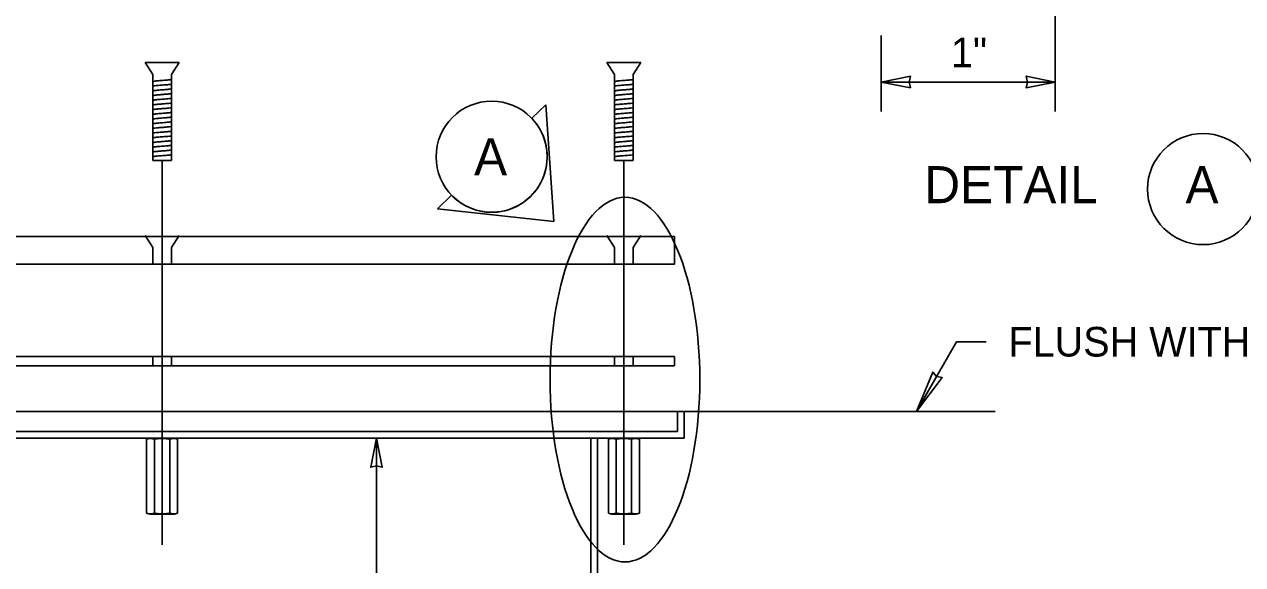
# Model space of a CAD drawing. Extents: x 99862 to 103680, y 99470 to 102076.
# Drawn here: x 101706 to 102364, y 100432 to 100724 of the extents above; entities that cross this region are included whole.
import ezdxf

# ---------------------------------------------------------------- set-up
doc = ezdxf.new("R2010")
doc.units = 0
for name, color, linetype in [('Level 1', 7, 'Continuous'), ('Level 10', 7, 'Continuous'), ('Level 15', 7, 'Continuous'), ('Level 16', 7, 'Continuous'), ('Level 17', 7, 'Continuous'), ('Level 2', 7, 'Continuous'), ('Level 20', 7, 'Continuous')]:
    doc.layers.add(name, color=color, linetype=linetype)

msp = doc.modelspace()

# ---------------------------------------------------------------- linework, layer by layer
at = {"layer": 'Level 1'}
for p, q in [((101248.49, 100515), (102062.21, 100515)), ((102058.64, 100504.1), (102058.64, 100515)), ((102062.21, 100500.54), (102062.21, 100515)), ((102062.21, 100500.54), (101248.49, 100500.54)), ((101252.06, 100504.1), (102058.64, 100504.1)), ((102011.78, 100460.54), (102011.78, 100500.54)), ((102015.35, 100136.47), (102015.35, 100500.54)), ((102011.78, 100400.54), (102011.78, 100460.54))]:
    msp.add_line(p, q, dxfattribs=at)
at = {"layer": 'Level 10'}
for p, q in [((101770.95, 100703.32), (101789.26, 100703.32)), ((101770.95, 100703.32), (101775.1, 100696.87)), ((101789.26, 100703.32), (101785.1, 100696.87)), ((102020.46, 100703.32), (102038.77, 100703.32)), ((102020.46, 100703.32), (102024.62, 100696.87)), ((102038.77, 100703.32), (102034.62, 100696.87)), ((101775.1, 100650.56), (101775.1, 100696.87)), ((101785.1, 100696.87), (101785.1, 100650.56)), ((102024.62, 100650.56), (102024.62, 100696.87)), ((102034.62, 100696.87), (102034.62, 100650.56)), ((101785.1, 100650.56), (101775.1, 100650.56)), ((102034.62, 100650.56), (102024.62, 100650.56)), ((101771.72, 100500.01), (101773.6, 100500.54)), ((101771.72, 100460.03), (101771.72, 100500.01)), ((101772.1, 100500.12), (101773.6, 100500.54)), ((101786.6, 100500.54), (101773.6, 100500.54)), ((101775.91, 100460.03), (101775.91, 100500.01)), ((101784.3, 100460.03), (101784.3, 100500.01)), ((101786.6, 100500.54), (101788.49, 100500.01)), ((101788.49, 100460.03), (101788.49, 100500.01)), ((102021.23, 100500.01), (102023.12, 100500.54)), ((102021.23, 100460.03), (102021.23, 100500.01)), ((102021.62, 100500.12), (102023.12, 100500.54)), ((102021.62, 100500.12), (102023.12, 100500.54)), ((102036.12, 100500.54), (102023.12, 100500.54)), ((102025.42, 100500.01), (102025.42, 100460.01)), ((102025.42, 100460.03), (102025.42, 100500.01)), ((102033.81, 100460.03), (102033.81, 100500.01)), ((102036.12, 100500.54), (102038, 100500.01)), ((102038, 100460.03), (102038, 100500.01)), ((101773.6, 100459.5), (101771.72, 100460.03)), ((101773.6, 100459.5), (101772.1, 100459.92)), ((101786.6, 100459.5), (101773.6, 100459.5)), ((101788.49, 100460.03), (101786.6, 100459.5)), ((102023.12, 100459.5), (102021.23, 100460.03)), ((102023.12, 100459.5), (102021.62, 100459.92)), ((102023.12, 100459.5), (102021.62, 100459.92)), ((102036.12, 100459.5), (102023.12, 100459.5)), ((102038, 100460.03), (102036.12, 100459.5))]:
    msp.add_line(p, q, dxfattribs=at)
for points, degree in [([(101775.11, 100693.12), (101775.2, 100693.18), (101775.75, 100693.32), (101777.96, 100693.54), (101781.5, 100693.81), (101784.15, 100694.05), (101784.95, 100694.2), (101785.1, 100694.26), (101785.11, 100694.26)], 3), ([(101775.11, 100690.59), (101775.16, 100690.62), (101775.43, 100690.71), (101776.64, 100690.89), (101779.52, 100691.13), (101782.66, 100691.37), (101784.46, 100691.57), (101784.97, 100691.67), (101785.11, 100691.72)], 3), ([(102024.62, 100693.12), (102024.71, 100693.18), (102025.26, 100693.32), (102027.47, 100693.54), (102031.01, 100693.81), (102033.66, 100694.05), (102034.46, 100694.2), (102034.61, 100694.26), (102034.62, 100694.26)], 3), ([(102024.62, 100690.59), (102024.68, 100690.62), (102024.94, 100690.71), (102026.16, 100690.89), (102029.03, 100691.13), (102032.17, 100691.37), (102033.97, 100691.57), (102034.48, 100691.67), (102034.62, 100691.72)], 3), ([(101775.11, 100688.05), (101775.13, 100688.06), (101775.35, 100688.17), (101776.63, 100688.35), (101779.25, 100688.57), (101781.72, 100688.76), (101783.91, 100688.95), (101784.88, 100689.1), (101785.1, 100689.18), (101785.11, 100689.19)], 3), ([(101775.11, 100685.51), (101775.16, 100685.55), (101775.5, 100685.65), (101776.73, 100685.81), (101778.93, 100686), (101781.45, 100686.2), (101783.98, 100686.42), (101784.91, 100686.57), (101785.11, 100686.65)], 3), ([(101775.11, 100682.97), (101775.16, 100683.01), (101775.58, 100683.14), (101777.42, 100683.34), (101780.81, 100683.61), (101783.46, 100683.83), (101784.73, 100684), (101785.03, 100684.08), (101785.11, 100684.11)], 3), ([(102024.62, 100688.05), (102024.64, 100688.06), (102024.86, 100688.17), (102026.14, 100688.35), (102028.77, 100688.57), (102031.23, 100688.76), (102033.42, 100688.95), (102034.39, 100689.1), (102034.61, 100689.18), (102034.62, 100689.19)], 3), ([(102024.62, 100685.51), (102024.68, 100685.55), (102025.01, 100685.65), (102026.24, 100685.81), (102028.44, 100686), (102030.96, 100686.2), (102033.49, 100686.42), (102034.42, 100686.57), (102034.62, 100686.65)], 3), ([(102024.62, 100682.97), (102024.68, 100683.01), (102025.09, 100683.14), (102026.93, 100683.34), (102030.32, 100683.61), (102032.97, 100683.83), (102034.24, 100684), (102034.55, 100684.08), (102034.62, 100684.11)], 3), ([(101775.11, 100680.44), (101775.16, 100680.47), (101775.5, 100680.58), (101776.73, 100680.73), (101778.93, 100680.93), (101781.45, 100681.12), (101783.98, 100681.34), (101784.91, 100681.49), (101785.11, 100681.57)], 3), ([(101775.11, 100677.9), (101775.16, 100677.93), (101775.5, 100678.04), (101776.73, 100678.19), (101778.93, 100678.39), (101781.45, 100678.58), (101783.98, 100678.8), (101784.91, 100678.96), (101785.11, 100679.03)], 3), ([(102024.62, 100680.44), (102024.68, 100680.47), (102025.01, 100680.58), (102026.24, 100680.73), (102028.44, 100680.93), (102030.96, 100681.12), (102033.49, 100681.34), (102034.42, 100681.49), (102034.62, 100681.57)], 3), ([(102024.62, 100677.9), (102024.68, 100677.93), (102025.01, 100678.04), (102026.24, 100678.19), (102028.44, 100678.39), (102030.96, 100678.58), (102033.49, 100678.8), (102034.42, 100678.96), (102034.62, 100679.03)], 3), ([(101775.11, 100675.36), (101775.16, 100675.39), (101775.58, 100675.52), (101777.42, 100675.73), (101780.81, 100675.99), (101783.46, 100676.21), (101784.73, 100676.39), (101785.04, 100676.47), (101785.11, 100676.49)], 3), ([(101775.11, 100672.82), (101775.16, 100672.86), (101775.5, 100672.96), (101776.73, 100673.12), (101779.2, 100673.34), (101781.78, 100673.53), (101784.07, 100673.75), (101784.88, 100673.87), (101785.1, 100673.95), (101785.11, 100673.96)], 3), ([(101775.11, 100670.28), (101775.2, 100670.34), (101775.77, 100670.47), (101777.96, 100670.7), (101781.5, 100670.97), (101784.15, 100671.21), (101784.95, 100671.36), (101785.1, 100671.41), (101785.11, 100671.42)], 3), ([(102024.62, 100675.36), (102024.68, 100675.39), (102025.09, 100675.52), (102026.93, 100675.73), (102030.32, 100675.99), (102032.97, 100676.21), (102034.24, 100676.39), (102034.55, 100676.47), (102034.62, 100676.49)], 3), ([(102024.62, 100672.82), (102024.68, 100672.86), (102025.01, 100672.96), (102026.24, 100673.12), (102028.71, 100673.34), (102031.29, 100673.53), (102033.58, 100673.75), (102034.39, 100673.87), (102034.61, 100673.95), (102034.62, 100673.96)], 3), ([(102024.62, 100670.28), (102024.72, 100670.34), (102025.28, 100670.47), (102027.47, 100670.7), (102031.01, 100670.97), (102033.66, 100671.21), (102034.46, 100671.36), (102034.61, 100671.41), (102034.62, 100671.42)], 3), ([(101775.11, 100667.75), (101775.16, 100667.78), (101775.5, 100667.89), (101776.92, 100668.07), (101779.26, 100668.26), (101782.03, 100668.48), (101784.22, 100668.68), (101784.97, 100668.83), (101785.11, 100668.88)], 3), ([(101775.11, 100665.21), (101775.16, 100665.24), (101775.5, 100665.35), (101776.73, 100665.5), (101778.93, 100665.7), (101781.45, 100665.89), (101783.98, 100666.11), (101784.91, 100666.26), (101785.11, 100666.34)], 3), ([(102024.62, 100667.75), (102024.68, 100667.78), (102025.02, 100667.89), (102026.43, 100668.07), (102028.77, 100668.26), (102031.54, 100668.48), (102033.74, 100668.68), (102034.49, 100668.83), (102034.62, 100668.88)], 3), ([(102024.62, 100665.21), (102024.68, 100665.24), (102025.01, 100665.35), (102026.24, 100665.5), (102028.44, 100665.7), (102030.96, 100665.89), (102033.49, 100666.11), (102034.42, 100666.26), (102034.62, 100666.34)], 3), ([(101775.11, 100662.67), (101775.16, 100662.7), (101775.58, 100662.83), (101777.42, 100663.04), (101780.81, 100663.3), (101783.46, 100663.52), (101784.73, 100663.7), (101785.03, 100663.77), (101785.11, 100663.8)], 3), ([(101775.11, 100660.13), (101775.16, 100660.16), (101775.5, 100660.27), (101776.73, 100660.43), (101779.2, 100660.64), (101781.78, 100660.84), (101784.06, 100661.05), (101784.88, 100661.18), (101785.1, 100661.26), (101785.11, 100661.27)], 3), ([(101775.11, 100657.59), (101775.2, 100657.65), (101775.77, 100657.78), (101777.96, 100658.01), (101781.5, 100658.27), (101784.15, 100658.52), (101784.95, 100658.67), (101785.1, 100658.72), (101785.11, 100658.73)], 3), ([(102024.62, 100662.67), (102024.68, 100662.7), (102025.09, 100662.83), (102026.93, 100663.04), (102030.32, 100663.3), (102032.97, 100663.52), (102034.24, 100663.7), (102034.55, 100663.77), (102034.62, 100663.8)], 3), ([(102024.62, 100660.13), (102024.68, 100660.16), (102025.01, 100660.27), (102026.24, 100660.43), (102028.71, 100660.64), (102031.29, 100660.84), (102033.58, 100661.05), (102034.39, 100661.18), (102034.61, 100661.26), (102034.62, 100661.27)], 3), ([(102024.62, 100657.59), (102024.72, 100657.65), (102025.28, 100657.78), (102027.47, 100658.01), (102031.01, 100658.27), (102033.66, 100658.52), (102034.46, 100658.67), (102034.61, 100658.72), (102034.62, 100658.73)], 3), ([(101775.11, 100655.05), (101775.16, 100655.09), (101775.5, 100655.19), (101776.92, 100655.37), (101779.25, 100655.57), (101782.03, 100655.78), (101784.22, 100655.98), (101784.97, 100656.14), (101785.11, 100656.19)], 3), ([(101775.11, 100652.51), (101775.2, 100652.57), (101775.75, 100652.7), (101777.96, 100652.93), (101781.5, 100653.2), (101784.15, 100653.44), (101784.95, 100653.59), (101785.1, 100653.64), (101785.11, 100653.65)], 3), ([(102024.62, 100655.05), (102024.68, 100655.09), (102025.02, 100655.19), (102026.43, 100655.37), (102028.77, 100655.57), (102031.54, 100655.78), (102033.74, 100655.98), (102034.48, 100656.14), (102034.62, 100656.19)], 3), ([(102024.62, 100652.51), (102024.71, 100652.57), (102025.26, 100652.7), (102027.47, 100652.93), (102031.01, 100653.2), (102033.66, 100653.44), (102034.46, 100653.59), (102034.61, 100653.64), (102034.62, 100653.65)], 3), ([(101771.72, 100500.01), (101773.12, 100500.44), (101774.51, 100500.43), (101775.91, 100500.01)], 2), ([(101775.91, 100500.01), (101778.69, 100500.46), (101781.52, 100500.41), (101784.3, 100500.01)], 2), ([(101784.3, 100500.01), (101785.69, 100500.44), (101787.09, 100500.43), (101788.49, 100500.01)], 2), ([(102021.23, 100500.01), (102022.63, 100500.44), (102024.03, 100500.43), (102025.42, 100500.01)], 2), ([(102025.42, 100500.01), (102028.2, 100500.46), (102031.03, 100500.41), (102033.81, 100500.01)], 2), ([(102033.81, 100500.01), (102035.21, 100500.44), (102036.6, 100500.43), (102038, 100500.01)], 2), ([(101771.72, 100460.03), (101773.12, 100459.6), (101774.51, 100459.61), (101775.91, 100460.03)], 2), ([(101775.91, 100460.03), (101778.69, 100459.58), (101781.52, 100459.63), (101784.3, 100460.03)], 2), ([(101784.3, 100460.03), (101785.69, 100459.6), (101787.09, 100459.61), (101788.49, 100460.03)], 2), ([(102021.23, 100460.03), (102022.63, 100459.6), (102024.03, 100459.61), (102025.42, 100460.03)], 2), ([(102025.42, 100460.03), (102028.2, 100459.58), (102031.03, 100459.63), (102033.81, 100460.03)], 2), ([(102033.81, 100460.03), (102035.21, 100459.6), (102036.6, 100459.61), (102038, 100460.03)], 2)]:
    msp.add_open_spline(points, degree=degree, dxfattribs=at)
at = {"layer": 'Level 15'}
for p, q in [((102262.71, 100925.18), (102262.71, 100676.85)), ((102168.71, 100717.97), (102168.71, 100676.85)), ((102262.71, 100692.85), (102168.71, 100692.85)), ((101780.1, 100650.56), (101780.1, 100442.92)), ((102029.62, 100650.56), (102029.62, 100442.92)), ((102187.67, 100515), (102209.39, 100552.62)), ((102225.39, 100552.62), (102209.39, 100552.62)), ((101895.97, 100500.54), (101895.97, 100140.04))]:
    msp.add_line(p, q, dxfattribs=at)
for points in [[(102168.71, 100692.85), (102184.43, 100689.76), (102183.7, 100692.85), (102184.43, 100695.93)], [(102262.71, 100692.85), (102246.98, 100689.76), (102247.71, 100692.85), (102246.98, 100695.93)], [(102187.67, 100515), (102201.67, 100533.28), (102198.56, 100533.86), (102196.5, 100536.26)], [(101895.97, 100500.54), (101892.88, 100484.81), (101895.97, 100485.54), (101899.05, 100484.81)]]:
    msp.add_lwpolyline(points, close=True, dxfattribs=at)
msp.add_ellipse((102030.2, 100532.15), major_axis=(0, 98.44), ratio=0.411064, dxfattribs=at)
at = {"layer": 'Level 16'}
for p, q in [((101252.61, 100609.44), (102056.9, 100609.44)), ((101775.1, 100603.51), (101770.95, 100609.96)), ((101785.1, 100603.51), (101789.26, 100609.96)), ((102024.62, 100603.51), (102020.46, 100609.96)), ((102034.62, 100603.51), (102038.77, 100609.96)), ((102056.9, 100609.44), (102056.9, 100594.44)), ((101775.1, 100594.95), (101775.1, 100603.51)), ((101785.1, 100594.95), (101785.1, 100603.51)), ((102024.62, 100594.95), (102024.62, 100603.51)), ((102034.62, 100594.95), (102034.62, 100603.51)), ((101252.61, 100594.44), (102056.9, 100594.44))]:
    msp.add_line(p, q, dxfattribs=at)
at = {"layer": 'Level 17'}
msp.add_line((102062.21, 100515), (102230.17, 100515), dxfattribs=at)
at = {"layer": 'Level 2'}
for p, q in [((102056.9, 100544.66), (101252.61, 100544.66)), ((101252.61, 100539.66), (102056.9, 100539.66)), ((101775.1, 100539.91), (101775.1, 100544.66)), ((101785.1, 100544.66), (101785.1, 100539.91)), ((102024.62, 100539.91), (102024.62, 100544.66)), ((102034.62, 100544.66), (102034.62, 100539.91)), ((102056.9, 100544.66), (102056.9, 100539.66))]:
    msp.add_line(p, q, dxfattribs=at)
at = {"layer": 'Level 20'}
for p, q in [((101987.5, 100680.58), (101979.84, 100673.25)), ((101991.68, 100617.5), (101987.5, 100680.58)), ((101936.5, 100631.77), (101928.84, 100624.44)), ((101928.84, 100624.44), (101991.68, 100617.5))]:
    msp.add_line(p, q, dxfattribs=at)
for centre in [(101958.17, 100652.51), (102342.56, 100635.05)]:
    msp.add_circle(centre, 30, dxfattribs=at)
msp.add_arc((101958.17, 100652.51), 30, 223.74134, 43.74577, dxfattribs=at)

# ---------------------------------------------------------------- texts
for s, p in [('1"', (102206.34, 100700.85)), ('FLUSH WITH SIDEWALK', (102237.39, 100544.62))]:
    msp.add_text(s, height=16, rotation=360, dxfattribs=at).set_placement(p)
for s, p in [('A', (101948.68, 100642.51)), ('DETAIL', (102191.97, 100627.43)), ('A', (102333.07, 100627.43))]:
    msp.add_text(s, height=20, dxfattribs=at).set_placement(p)

doc.saveas('drawing.dxf')
